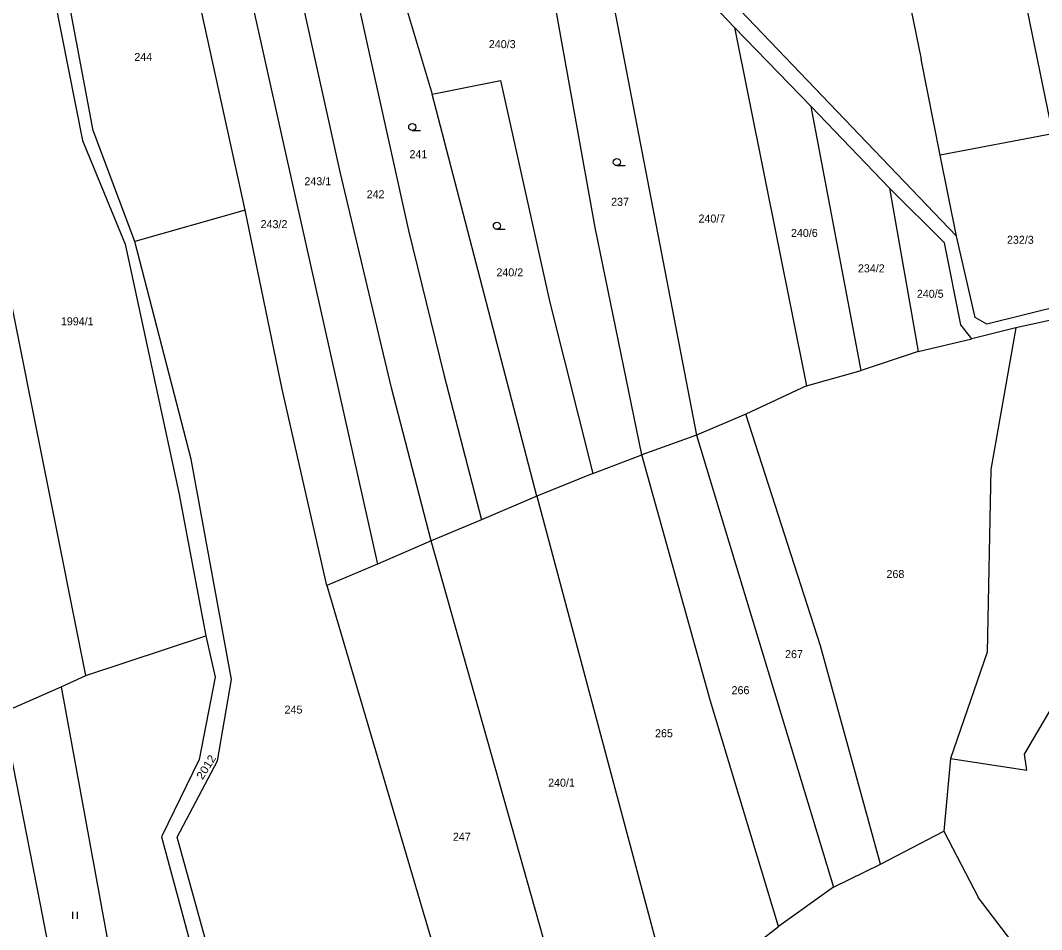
# Model space of a CAD drawing. Extents: x -820420 to -815896, y -1105820 to -1103643.
# Drawn here: x -817609.6 to -817392.6, y -1105298 to -1105104.9 of the extents above; entities that cross this region are included whole.
import ezdxf
from ezdxf.enums import TextEntityAlignment as Align

# ---------------------------------------------------------------- set-up
doc = ezdxf.new("R2010")
doc.units = 0
doc.header["$LTSCALE"] = 0.68
doc.layers.add('1', color=7, linetype='Continuous', lineweight=25)
doc.layers.add('3', color=7, linetype='Continuous', lineweight=25)
doc.layers.add('2', color=7, linetype='Continuous')

msp = doc.modelspace()

# ---------------------------------------------------------------- linework, layer by layer
at = {"layer": '1'}
for p, q in [((-817407.13, -1105047.39), (-817390.32, -1105128.96)), ((-817430.04, -1105055.73), (-817418.25, -1105113.09)), ((-817547.45, -1105058.03), (-817527.17, -1105149.52)), ((-817541.67, -1105137.03), (-817558.09, -1105063.32)), ((-817567.99, -1105067.03), (-817551.11, -1105142.93)), ((-817561.87, -1105145.2), (-817578.15, -1105070.92)), ((-817486.12, -1105088.22), (-817465.96, -1105192.95)), ((-817457.92, -1105106.42), (-817476.9, -1105086.16)), ((-817531.1, -1105090.58), (-817522.16, -1105120.58)), ((-817603.17, -1105096.45), (-817596.43, -1105130.36)), ((-817594.18, -1105128.25), (-817600.09, -1105096.83)), ((-817487.5, -1105148.9), (-817496.75, -1105097.45)), ((-817456.69, -1105102.72), (-817410.71, -1105150.7)), ((-817441.63, -1105123.14), (-817457.92, -1105106.42)), ((-817457.92, -1105106.42), (-817442.58, -1105182.49)), ((-817414.16, -1105133.48), (-817418.25, -1105113.09)), ((-817522.16, -1105120.58), (-817507.62, -1105117.66)), ((-817507.62, -1105117.66), (-817497.17, -1105164.77)), ((-817499.89, -1105205.97), (-817522.16, -1105120.58)), ((-817424.93, -1105140.49), (-817441.63, -1105123.14)), ((-817430.99, -1105179.25), (-817441.63, -1105123.14)), ((-817585.34, -1105151.88), (-817594.18, -1105128.25)), ((-817390.32, -1105128.96), (-817414.16, -1105133.48)), ((-817596.43, -1105130.36), (-817587.36, -1105152.43)), ((-817410.71, -1105150.7), (-817414.16, -1105133.48)), ((-817530.8, -1105182.9), (-817541.67, -1105137.03)), ((-817424.93, -1105140.49), (-817418.85, -1105175.2)), ((-817413.29, -1105152.15), (-817424.93, -1105140.49)), ((-817551.11, -1105142.93), (-817533.74, -1105220.38)), ((-817561.87, -1105145.2), (-817585.34, -1105151.88)), ((-817554.01, -1105183.23), (-817561.87, -1105145.2)), ((-817477.57, -1105197.16), (-817487.5, -1105148.9)), ((-817527.17, -1105149.52), (-817519.69, -1105180.09)), ((-817406.75, -1105167.96), (-817410.71, -1105150.7)), ((-817587.36, -1105152.43), (-817575.95, -1105205.25)), ((-817573.34, -1105198.09), (-817585.34, -1105151.88)), ((-817409.78, -1105169.54), (-817413.29, -1105152.15)), ((-817595.77, -1105244), (-817612.44, -1105160.35)), ((-817382.1, -1105163.92), (-817404.3, -1105169.4)), ((-817497.17, -1105164.77), (-817488.02, -1105201.09)), ((-817378.9, -1105165.91), (-817398.08, -1105170.21)), ((-817404.3, -1105169.4), (-817406.75, -1105167.96)), ((-817407.48, -1105172.49), (-817409.78, -1105169.54)), ((-817398.08, -1105170.21), (-817407.48, -1105172.49)), ((-817398.08, -1105170.21), (-817403.43, -1105200.3)), ((-817418.85, -1105175.2), (-817407.48, -1105172.49)), ((-817418.85, -1105175.2), (-817430.99, -1105179.25)), ((-817442.58, -1105182.49), (-817430.99, -1105179.25)), ((-817519.69, -1105180.09), (-817511.66, -1105211)), ((-817544.49, -1105224.92), (-817554.01, -1105183.23)), ((-817522.36, -1105215.46), (-817530.8, -1105182.9)), ((-817442.58, -1105182.49), (-817455.46, -1105188.49)), ((-817455.46, -1105188.49), (-817465.96, -1105192.95)), ((-817439.64, -1105237.75), (-817455.46, -1105188.49)), ((-817465.96, -1105192.95), (-817477.57, -1105197.16)), ((-817465.96, -1105192.95), (-817436.86, -1105288.99)), ((-817564.76, -1105244.91), (-817573.34, -1105198.09)), ((-817488.02, -1105201.09), (-817477.57, -1105197.16)), ((-817463.02, -1105249.46), (-817477.57, -1105197.16)), ((-817488.02, -1105201.09), (-817499.89, -1105205.97)), ((-817403.43, -1105200.3), (-817404.22, -1105239.08)), ((-817396.24, -1105260.73), (-817361.19, -1105200.55)), ((-817575.95, -1105205.25), (-817570.22, -1105235.61)), ((-817499.89, -1105205.97), (-817511.66, -1105211)), ((-817499.89, -1105205.97), (-817470.8, -1105314.9)), ((-817511.66, -1105211), (-817522.36, -1105215.46)), ((-817522.36, -1105215.46), (-817533.74, -1105220.38)), ((-817489.93, -1105330.21), (-817522.36, -1105215.46)), ((-817533.74, -1105220.38), (-817544.49, -1105224.92)), ((-817544.49, -1105224.92), (-817510.57, -1105340.06)), ((-817595.77, -1105244), (-817570.22, -1105235.61)), ((-817570.22, -1105235.61), (-817568.24, -1105244.39)), ((-817426.85, -1105284.12), (-817439.64, -1105237.75)), ((-817404.22, -1105239.08), (-817412.01, -1105261.63)), ((-817601.01, -1105246.44), (-817595.77, -1105244)), ((-817568.24, -1105244.39), (-817571.66, -1105261.91)), ((-817613.38, -1105251.91), (-817601.01, -1105246.44)), ((-817601.01, -1105246.44), (-817589.78, -1105307.73)), ((-817567.76, -1105262.18), (-817564.76, -1105244.91)), ((-817448.56, -1105297.38), (-817463.02, -1105249.46)), ((-817605.36, -1105292.66), (-817613.38, -1105251.91)), ((-817412.01, -1105261.63), (-817413.4, -1105277.09)), ((-817412.01, -1105261.63), (-817395.74, -1105264.12)), ((-817395.74, -1105264.12), (-817396.24, -1105260.73)), ((-817571.66, -1105261.91), (-817579.64, -1105278.33)), ((-817576.32, -1105278.4), (-817567.76, -1105262.18)), ((-817579.64, -1105278.33), (-817572.81, -1105303.65)), ((-817568.35, -1105307.09), (-817576.32, -1105278.4)), ((-817426.85, -1105284.12), (-817413.4, -1105277.09)), ((-817413.4, -1105277.09), (-817406.05, -1105291.29)), ((-817436.86, -1105288.99), (-817426.85, -1105284.12)), ((-817436.86, -1105288.99), (-817448.56, -1105297.38)), ((-817398.95, -1105300.53), (-817406.05, -1105291.29)), ((-817592.59, -1105359.31), (-817605.36, -1105292.66)), ((-817460.71, -1105306.72), (-817448.56, -1105297.38))]:
    msp.add_line(p, q, dxfattribs=at)
at = {"layer": '3'}
for p, q in [((-817526.373, -1105128.27), (-817524.623, -1105128.27)), ((-817482.893, -1105135.73), (-817481.143, -1105135.73)), ((-817508.383, -1105149.25), (-817506.633, -1105149.25)), ((-817598.501, -1105295.7), (-817598.501, -1105294.2)), ((-817597.5, -1105295.7), (-817597.5, -1105294.2))]:
    msp.add_line(p, q, dxfattribs=at)
for centre in [(-817526.3729, -1105127.5198), (-817482.8929, -1105134.9798), (-817508.3829, -1105148.4998)]:
    msp.add_circle(centre, 0.75, dxfattribs=at)

# ---------------------------------------------------------------- texts
at = {"layer": '2'}
for s, p in [('240/3', (-817507.25, -1105110.775)), ('244', (-817583.539, -1105113.495)), ('241', (-817525.069, -1105134.145)), ('243/1', (-817546.45, -1105139.895)), ('242', (-817534.169, -1105142.665)), ('237', (-817482.219, -1105144.265)), ('240/7', (-817462.7, -1105147.815)), ('243/2', (-817555.75, -1105149.005)), ('240/6', (-817443.05, -1105150.875)), ('232/3', (-817397.15, -1105152.335)), ('240/2', (-817505.64, -1105159.245)), ('234/2', (-817428.82, -1105158.405)), ('240/5', (-817416.3, -1105163.805)), ('1994/1', (-817597.56, -1105169.655)), ('268', (-817423.699, -1105223.325)), ('267', (-817445.249, -1105240.345)), ('266', (-817456.619, -1105248.005)), ('245', (-817551.609, -1105252.125)), ('265', (-817472.879, -1105257.145)), ('240/1', (-817494.66, -1105267.645)), ('247', (-817515.839, -1105279.135))]:
    msp.add_text(s, height=1.7, dxfattribs=at).set_placement(p, align=Align.CENTER)
at = {"layer": '2', "width": 1.1}
msp.add_text('2012', height=1.7, rotation=58, dxfattribs=at).set_placement((-817569.4559, -1105263.9259), align=Align.CENTER)

doc.saveas('drawing.dxf')
